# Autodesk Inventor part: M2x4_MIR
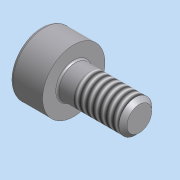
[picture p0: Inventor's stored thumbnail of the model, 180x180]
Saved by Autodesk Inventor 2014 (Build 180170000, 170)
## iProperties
Created: 2015-05
Part Number: M2x4_MIR
Material: 일반
Vendor: CBT Solutions
Document SubType Name: 모델링
Designer: Administrator
Appearance: 기본값
Company: 한국ATC센터
Author: KYOUNG IL JANG
Comments: 파생
d0: 1.000 ul
d0_1: 1.000 ul
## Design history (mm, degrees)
derived "M2x4.ipt" dims count "d0" = 1
feature "솔리드1::M2x4.ipt" dims count "d0" = 1
tag "피쳐 태그1"
node "솔리드1"
other parameters: "d0_1" = 1
